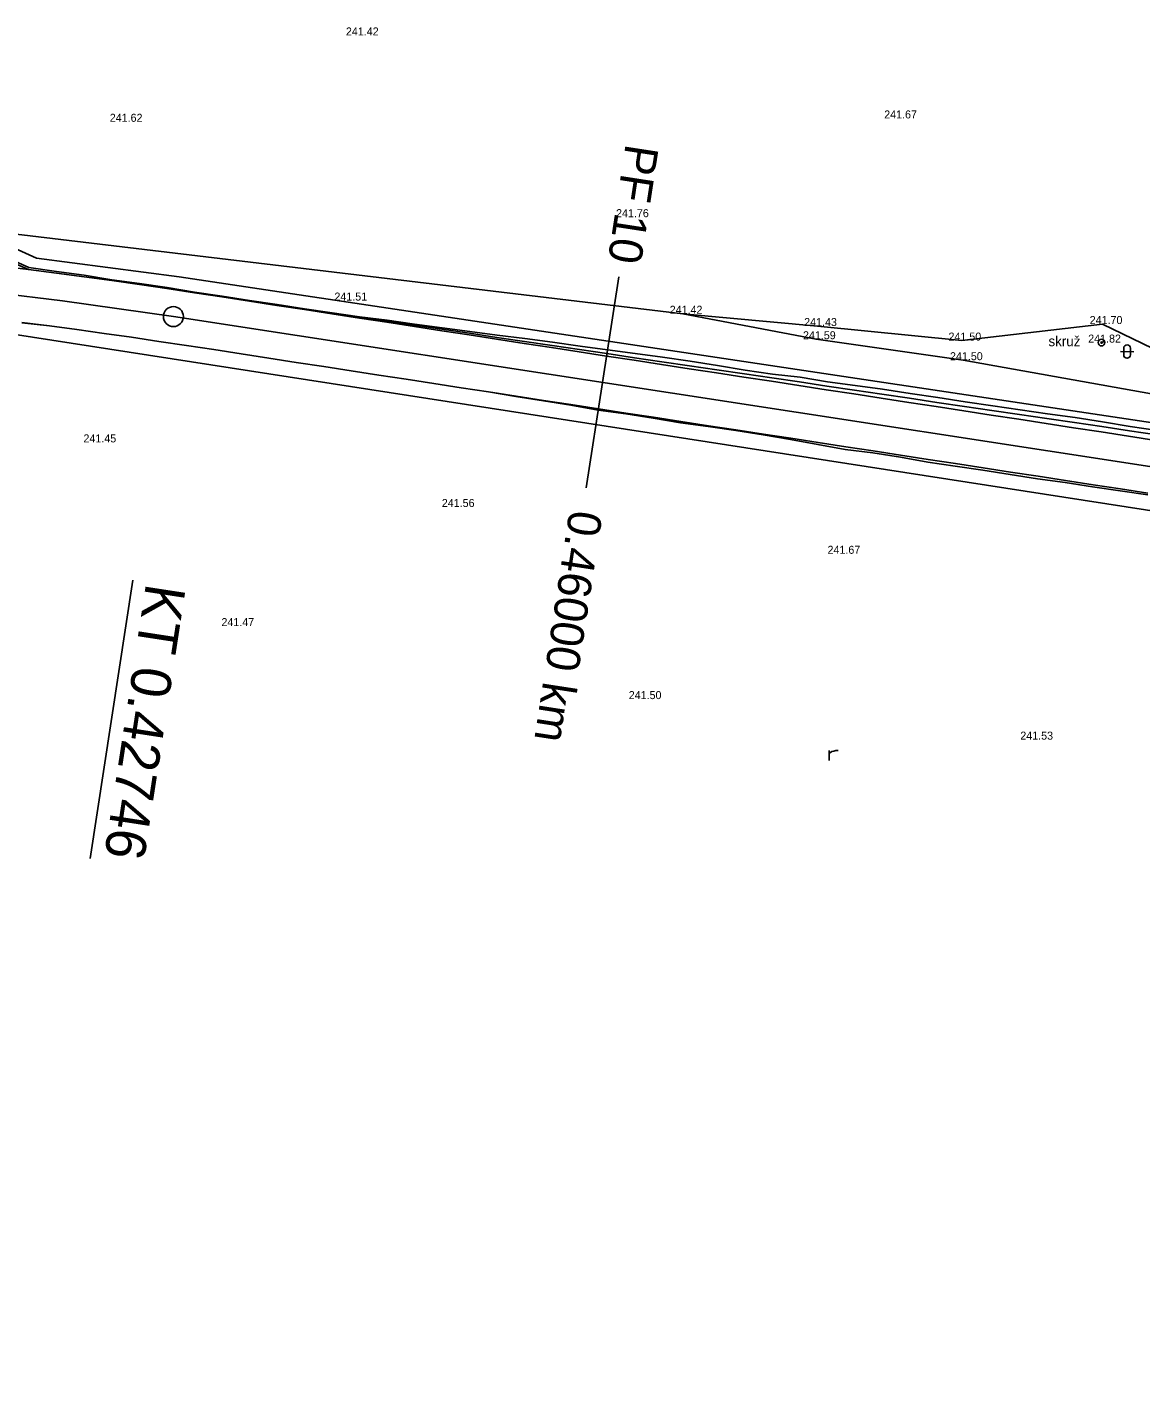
# Model space of a CAD drawing. Extents: x -555887 to -552101, y -1100251 to -1096546.
# Drawn here: x -554264.7 to -554181.3, y -1098461.3 to -1098358.9 of the extents above; entities that cross this region are included whole.
import ezdxf

# ---------------------------------------------------------------- set-up
doc = ezdxf.new("R2010")
doc.units = 0
for name, color, linetype in [('PARCELY_cesty', 7, 'Continuous'), ('POLYGONY_SITUACE_PF', 7, 'Continuous'), ('POLYGONY_SITUACE_PF_POPISY', 7, 'Continuous'), ('POLYGONY_SITUACE_PO', 7, 'Continuous'), ('Výškopis', 7, 'Continuous'), ('ZSST', 7, 'Continuous'), ('zájem', 7, 'Continuous')]:
    doc.layers.add(name, color=color, linetype=linetype)

msp = doc.modelspace()

# ---------------------------------------------------------------- linework, layer by layer
msp.add_line((-554256.8, -1098400.3), (-554260, -1098421.15))
at = {"layer": 'PARCELY_cesty'}
msp.add_lwpolyline([(-554666.58, -1098424.3), (-554661.61, -1098426.35), (-554474.62, -1098365.56), (-554470, -1098364.25), (-554462.92, -1098363), (-554455.97, -1098362.75), (-554451.05, -1098362.62), (-554296.95, -1098373.16), (-554290.89, -1098371.6), (-554270.39, -1098373.3), (-554264.04, -1098376.17), (-554253.34, -1098377.56), (-554081.03, -1098403.4), (-554065.66, -1098405.31), (-554039.82, -1098406.01), (-554011.2, -1098408.42), (-553994.13, -1098410.89)], dxfattribs=at)
at = {"layer": 'POLYGONY_SITUACE_PF'}
for p, q in [((-554220.39, -1098377.57), (-554221.6, -1098385.47)), ((-554221.6, -1098385.47), (-554222.82, -1098393.38))]:
    msp.add_line(p, q, dxfattribs=at)
at = {"layer": 'POLYGONY_SITUACE_PO'}
for p, q in [((-554266.63, -1098376.14), (-554264.62, -1098377.01)), ((-554266.6, -1098375.95), (-554264.6, -1098376.87)), ((-554266.7, -1098376.75), (-554264.62, -1098377.01)), ((-554264.62, -1098377.01), (-554262.54, -1098377.28)), ((-554264.62, -1098377.01), (-554262.54, -1098377.28)), ((-554264.6, -1098376.87), (-554262.53, -1098377.17)), ((-554262.54, -1098377.28), (-554260.47, -1098377.55)), ((-554262.54, -1098377.28), (-554260.47, -1098377.55)), ((-554262.53, -1098377.17), (-554260.45, -1098377.44)), ((-554260.45, -1098377.44), (-554258.39, -1098377.78)), ((-554270.44, -1098378.33), (-554262.09, -1098379.35)), ((-554260.47, -1098377.55), (-554258.39, -1098377.83)), ((-554260.47, -1098377.55), (-554258.39, -1098377.83)), ((-554258.39, -1098377.78), (-554256.31, -1098378.05)), ((-554258.39, -1098377.83), (-554256.32, -1098378.13)), ((-554258.39, -1098377.83), (-554256.32, -1098378.13)), ((-554256.32, -1098378.13), (-554254.25, -1098378.44)), ((-554256.32, -1098378.13), (-554254.25, -1098378.44)), ((-554256.31, -1098378.05), (-554254.24, -1098378.37)), ((-554254.25, -1098378.44), (-554252.19, -1098378.75)), ((-554254.25, -1098378.44), (-554252.19, -1098378.75)), ((-554254.24, -1098378.37), (-554252.18, -1098378.7)), ((-554262.09, -1098379.35), (-554253.77, -1098380.54)), ((-554252.19, -1098378.75), (-554250.13, -1098379.05)), ((-554252.19, -1098378.75), (-554250.13, -1098379.07)), ((-554252.18, -1098378.7), (-554250.12, -1098379.01)), ((-554250.13, -1098379.05), (-554248.06, -1098379.36)), ((-554250.13, -1098379.07), (-554248.07, -1098379.39)), ((-554250.12, -1098379.01), (-554248.06, -1098379.33)), ((-554248.07, -1098379.39), (-554246.01, -1098379.7)), ((-554248.06, -1098379.33), (-554246, -1098379.64)), ((-554248.06, -1098379.36), (-554246, -1098379.66)), ((-554253.77, -1098380.54), (-554081.59, -1098406.98)), ((-554246.01, -1098379.7), (-554243.95, -1098380.02)), ((-554246, -1098379.64), (-554243.94, -1098379.95)), ((-554246, -1098379.66), (-554243.94, -1098379.96)), ((-554243.95, -1098380.02), (-554241.89, -1098380.34)), ((-554243.94, -1098379.95), (-554241.88, -1098380.26)), ((-554243.94, -1098379.96), (-554241.88, -1098380.27)), ((-554241.89, -1098380.34), (-554239.83, -1098380.65)), ((-554241.88, -1098380.26), (-554239.82, -1098380.57)), ((-554241.88, -1098380.27), (-554239.82, -1098380.57)), ((-554265.12, -1098380.98), (-554263.06, -1098381.24)), ((-554265.12, -1098380.98), (-554263.06, -1098381.24)), ((-554265.12, -1098381.02), (-554263.06, -1098381.24)), ((-554263.06, -1098381.24), (-554261.01, -1098381.51)), ((-554263.06, -1098381.24), (-554263.06, -1098381.24)), ((-554263.06, -1098381.24), (-554261.01, -1098381.51)), ((-554263.06, -1098381.24), (-554261.01, -1098381.51)), ((-554261.01, -1098381.51), (-554258.95, -1098381.8)), ((-554261.01, -1098381.51), (-554258.95, -1098381.8)), ((-554261.01, -1098381.51), (-554258.95, -1098381.8)), ((-554239.83, -1098380.65), (-554237.77, -1098380.97)), ((-554239.82, -1098380.57), (-554237.75, -1098380.81)), ((-554239.82, -1098380.57), (-554237.76, -1098380.88)), ((-554237.77, -1098380.97), (-554235.71, -1098381.28)), ((-554237.76, -1098380.88), (-554235.7, -1098381.18)), ((-554237.75, -1098380.81), (-554235.69, -1098381.12)), ((-554235.71, -1098381.28), (-554233.65, -1098381.6)), ((-554235.7, -1098381.18), (-554233.64, -1098381.49)), ((-554235.69, -1098381.12), (-554233.62, -1098381.38)), ((-554233.64, -1098381.49), (-554231.58, -1098381.79)), ((-554233.62, -1098381.38), (-554231.56, -1098381.66)), ((-554258.95, -1098381.8), (-554256.9, -1098382.09)), ((-554258.95, -1098381.8), (-554256.9, -1098382.09)), ((-554258.95, -1098381.8), (-554256.9, -1098382.09)), ((-554256.9, -1098382.09), (-554254.85, -1098382.4)), ((-554256.9, -1098382.09), (-554254.85, -1098382.4)), ((-554256.9, -1098382.09), (-554254.85, -1098382.4)), ((-554254.85, -1098382.4), (-554252.79, -1098382.71)), ((-554254.85, -1098382.4), (-554252.79, -1098382.71)), ((-554254.85, -1098382.4), (-554252.79, -1098382.71)), ((-554233.65, -1098381.6), (-554231.6, -1098381.92)), ((-554231.6, -1098381.92), (-554229.54, -1098382.23)), ((-554231.58, -1098381.79), (-554229.52, -1098382.1)), ((-554231.56, -1098381.66), (-554229.49, -1098381.94)), ((-554229.54, -1098382.23), (-554227.48, -1098382.55)), ((-554229.52, -1098382.1), (-554227.45, -1098382.4)), ((-554229.49, -1098381.94), (-554227.42, -1098382.19)), ((-554227.48, -1098382.55), (-554225.42, -1098382.87)), ((-554227.45, -1098382.4), (-554225.39, -1098382.7)), ((-554227.42, -1098382.19), (-554225.36, -1098382.47)), ((-554225.36, -1098382.47), (-554223.29, -1098382.75)), ((-554252.79, -1098382.71), (-554250.74, -1098383.02)), ((-554252.79, -1098382.71), (-554250.74, -1098383.02)), ((-554252.79, -1098382.71), (-554250.74, -1098383.02)), ((-554250.74, -1098383.02), (-554248.68, -1098383.34)), ((-554250.74, -1098383.02), (-554248.68, -1098383.34)), ((-554250.74, -1098383.02), (-554248.68, -1098383.34)), ((-554248.68, -1098383.34), (-554246.62, -1098383.66)), ((-554248.68, -1098383.34), (-554246.62, -1098383.66)), ((-554248.68, -1098383.34), (-554246.62, -1098383.66)), ((-554225.42, -1098382.87), (-554223.36, -1098383.18)), ((-554225.39, -1098382.7), (-554223.33, -1098383.01)), ((-554223.36, -1098383.18), (-554221.3, -1098383.5)), ((-554223.33, -1098383.01), (-554221.27, -1098383.31)), ((-554223.29, -1098382.75), (-554221.23, -1098383.04)), ((-554221.3, -1098383.5), (-554219.24, -1098383.81)), ((-554221.27, -1098383.31), (-554219.21, -1098383.62)), ((-554221.23, -1098383.04), (-554219.16, -1098383.3)), ((-554219.21, -1098383.62), (-554217.15, -1098383.92)), ((-554219.16, -1098383.3), (-554217.1, -1098383.58)), ((-554217.1, -1098383.58), (-554215.04, -1098383.89)), ((-554246.62, -1098383.66), (-554244.56, -1098383.97)), ((-554246.62, -1098383.66), (-554244.56, -1098383.97)), ((-554246.62, -1098383.66), (-554244.56, -1098383.97)), ((-554244.56, -1098383.97), (-554242.5, -1098384.29)), ((-554244.56, -1098383.97), (-554242.5, -1098384.29)), ((-554244.56, -1098383.97), (-554242.5, -1098384.29)), ((-554242.5, -1098384.29), (-554240.44, -1098384.61)), ((-554242.5, -1098384.29), (-554240.44, -1098384.61)), ((-554242.5, -1098384.29), (-554240.44, -1098384.61)), ((-554240.44, -1098384.61), (-554238.38, -1098384.92)), ((-554240.44, -1098384.61), (-554238.38, -1098384.92)), ((-554240.44, -1098384.61), (-554238.38, -1098384.92)), ((-554219.24, -1098383.81), (-554217.18, -1098384.13)), ((-554217.18, -1098384.13), (-554215.12, -1098384.45)), ((-554217.15, -1098383.92), (-554215.09, -1098384.23)), ((-554215.12, -1098384.45), (-554213.06, -1098384.76)), ((-554215.09, -1098384.23), (-554213.03, -1098384.53)), ((-554215.04, -1098383.89), (-554212.98, -1098384.21)), ((-554213.03, -1098384.53), (-554210.97, -1098384.83)), ((-554212.98, -1098384.21), (-554210.92, -1098384.56)), ((-554210.92, -1098384.56), (-554208.86, -1098384.85)), ((-554238.38, -1098384.92), (-554236.32, -1098385.24)), ((-554238.38, -1098384.92), (-554236.32, -1098385.24)), ((-554238.38, -1098384.92), (-554236.32, -1098385.24)), ((-554236.32, -1098385.24), (-554234.26, -1098385.55)), ((-554236.32, -1098385.24), (-554234.26, -1098385.55)), ((-554236.32, -1098385.24), (-554234.26, -1098385.55)), ((-554234.26, -1098385.55), (-554232.2, -1098385.87)), ((-554234.26, -1098385.55), (-554232.2, -1098385.87)), ((-554234.26, -1098385.55), (-554232.2, -1098385.87)), ((-554213.06, -1098384.76), (-554211, -1098385.08)), ((-554211, -1098385.08), (-554208.94, -1098385.39)), ((-554210.97, -1098384.83), (-554208.91, -1098385.14)), ((-554208.94, -1098385.39), (-554206.89, -1098385.71)), ((-554208.91, -1098385.14), (-554206.84, -1098385.44)), ((-554208.86, -1098384.85), (-554206.79, -1098385.08)), ((-554206.84, -1098385.44), (-554204.78, -1098385.75)), ((-554206.79, -1098385.08), (-554204.74, -1098385.43)), ((-554204.74, -1098385.43), (-554202.67, -1098385.71)), ((-554232.2, -1098385.87), (-554230.14, -1098386.19)), ((-554232.2, -1098385.87), (-554230.14, -1098386.19)), ((-554232.2, -1098385.87), (-554230.14, -1098386.19)), ((-554230.14, -1098386.19), (-554228.08, -1098386.5)), ((-554230.14, -1098386.19), (-554230.14, -1098386.19)), ((-554230.14, -1098386.19), (-554228.09, -1098386.53)), ((-554230.14, -1098386.19), (-554228.08, -1098386.5)), ((-554228.09, -1098386.53), (-554226.03, -1098386.86)), ((-554228.08, -1098386.5), (-554226.03, -1098386.82)), ((-554228.08, -1098386.5), (-554226.03, -1098386.82)), ((-554206.89, -1098385.71), (-554204.83, -1098386.03)), ((-554204.83, -1098386.03), (-554202.77, -1098386.34)), ((-554204.78, -1098385.75), (-554202.72, -1098386.05)), ((-554202.77, -1098386.34), (-554200.71, -1098386.66)), ((-554202.72, -1098386.05), (-554200.66, -1098386.36)), ((-554202.67, -1098385.71), (-554200.61, -1098385.99)), ((-554200.71, -1098386.66), (-554198.65, -1098386.98)), ((-554200.66, -1098386.36), (-554198.6, -1098386.66)), ((-554200.61, -1098385.99), (-554198.55, -1098386.31)), ((-554198.6, -1098386.66), (-554196.54, -1098386.97)), ((-554198.55, -1098386.31), (-554196.48, -1098386.6)), ((-554196.48, -1098386.6), (-554194.42, -1098386.92)), ((-554226.03, -1098386.82), (-554223.97, -1098387.13)), ((-554226.03, -1098386.82), (-554223.97, -1098387.13)), ((-554226.03, -1098386.86), (-554223.97, -1098387.19)), ((-554223.97, -1098387.13), (-554221.91, -1098387.45)), ((-554223.97, -1098387.13), (-554221.91, -1098387.45)), ((-554223.97, -1098387.19), (-554221.92, -1098387.55)), ((-554221.92, -1098387.55), (-554219.86, -1098387.84)), ((-554221.91, -1098387.45), (-554219.85, -1098387.77)), ((-554221.91, -1098387.45), (-554219.85, -1098387.77)), ((-554198.65, -1098386.98), (-554196.59, -1098387.29)), ((-554196.59, -1098387.29), (-554194.53, -1098387.61)), ((-554196.54, -1098386.97), (-554194.48, -1098387.27)), ((-554194.53, -1098387.61), (-554192.47, -1098387.92)), ((-554194.48, -1098387.27), (-554192.42, -1098387.57)), ((-554194.42, -1098386.92), (-554192.36, -1098387.23)), ((-554192.42, -1098387.57), (-554190.36, -1098387.88)), ((-554192.36, -1098387.23), (-554190.3, -1098387.52)), ((-554190.3, -1098387.52), (-554188.24, -1098387.82)), ((-554219.86, -1098387.84), (-554217.8, -1098388.16)), ((-554219.85, -1098387.77), (-554217.79, -1098388.08)), ((-554219.85, -1098387.77), (-554217.79, -1098388.08)), ((-554217.8, -1098388.16), (-554215.75, -1098388.51)), ((-554217.79, -1098388.08), (-554215.73, -1098388.4)), ((-554217.79, -1098388.08), (-554215.73, -1098388.4)), ((-554215.75, -1098388.51), (-554213.68, -1098388.79)), ((-554215.73, -1098388.4), (-554213.67, -1098388.72)), ((-554215.73, -1098388.4), (-554213.67, -1098388.72)), ((-554213.67, -1098388.72), (-554211.61, -1098389.03)), ((-554213.67, -1098388.72), (-554211.61, -1098389.03)), ((-554192.47, -1098387.92), (-554190.41, -1098388.24)), ((-554190.41, -1098388.24), (-554188.35, -1098388.56)), ((-554190.36, -1098387.88), (-554188.3, -1098388.18)), ((-554188.35, -1098388.56), (-554186.29, -1098388.87)), ((-554188.3, -1098388.18), (-554186.23, -1098388.49)), ((-554188.24, -1098387.82), (-554186.18, -1098388.11)), ((-554186.23, -1098388.49), (-554184.17, -1098388.79)), ((-554186.18, -1098388.11), (-554184.12, -1098388.44)), ((-554184.12, -1098388.44), (-554182.06, -1098388.77)), ((-554213.68, -1098388.79), (-554211.62, -1098389.09)), ((-554211.62, -1098389.09), (-554209.56, -1098389.41)), ((-554211.61, -1098389.03), (-554209.55, -1098389.35)), ((-554211.61, -1098389.03), (-554209.55, -1098389.35)), ((-554209.56, -1098389.41), (-554207.51, -1098389.76)), ((-554209.55, -1098389.35), (-554207.49, -1098389.66)), ((-554209.55, -1098389.35), (-554207.49, -1098389.66)), ((-554207.51, -1098389.76), (-554205.46, -1098390.13)), ((-554207.49, -1098389.66), (-554205.43, -1098389.98)), ((-554207.49, -1098389.66), (-554205.43, -1098389.98)), ((-554186.29, -1098388.87), (-554184.23, -1098389.19)), ((-554184.23, -1098389.19), (-554182.18, -1098389.51)), ((-554184.17, -1098388.79), (-554182.11, -1098389.1)), ((-554182.18, -1098389.51), (-554180.12, -1098389.82)), ((-554182.11, -1098389.1), (-554180.05, -1098389.4)), ((-554182.06, -1098388.77), (-554180, -1098389.09)), ((-554205.46, -1098390.13), (-554203.41, -1098390.5)), ((-554205.43, -1098389.98), (-554203.37, -1098390.3)), ((-554205.43, -1098389.98), (-554203.37, -1098390.3)), ((-554203.41, -1098390.5), (-554201.34, -1098390.76)), ((-554203.37, -1098390.3), (-554201.31, -1098390.61)), ((-554203.37, -1098390.3), (-554201.31, -1098390.61)), ((-554201.34, -1098390.76), (-554199.28, -1098391.07)), ((-554201.31, -1098390.61), (-554199.26, -1098390.93)), ((-554201.31, -1098390.61), (-554199.26, -1098390.93)), ((-554199.28, -1098391.07), (-554197.23, -1098391.44)), ((-554199.26, -1098390.93), (-554197.2, -1098391.25)), ((-554199.26, -1098390.93), (-554197.2, -1098391.25)), ((-554197.23, -1098391.44), (-554195.17, -1098391.75)), ((-554197.2, -1098391.25), (-554195.14, -1098391.56)), ((-554197.2, -1098391.25), (-554195.14, -1098391.56)), ((-554195.17, -1098391.75), (-554193.11, -1098392.06)), ((-554195.14, -1098391.56), (-554193.08, -1098391.88)), ((-554195.14, -1098391.56), (-554193.08, -1098391.88)), ((-554193.11, -1098392.06), (-554191.05, -1098392.37)), ((-554193.08, -1098391.88), (-554191.02, -1098392.19)), ((-554193.08, -1098391.88), (-554191.02, -1098392.19)), ((-554191.05, -1098392.37), (-554188.99, -1098392.69)), ((-554191.02, -1098392.19), (-554188.96, -1098392.51)), ((-554191.02, -1098392.19), (-554188.96, -1098392.51)), ((-554188.99, -1098392.69), (-554186.92, -1098392.98)), ((-554188.96, -1098392.51), (-554186.9, -1098392.83)), ((-554188.96, -1098392.51), (-554186.9, -1098392.83)), ((-554186.9, -1098392.83), (-554184.84, -1098393.14)), ((-554186.9, -1098392.83), (-554184.84, -1098393.14)), ((-554186.92, -1098392.98), (-554184.87, -1098393.31)), ((-554184.87, -1098393.31), (-554182.81, -1098393.61)), ((-554184.84, -1098393.14), (-554182.78, -1098393.46)), ((-554184.84, -1098393.14), (-554182.78, -1098393.46)), ((-554182.81, -1098393.61), (-554180.74, -1098393.9)), ((-554182.78, -1098393.46), (-554180.72, -1098393.78)), ((-554182.78, -1098393.46), (-554180.72, -1098393.78))]:
    msp.add_line(p, q, dxfattribs=at)
msp.add_circle((-554253.77, -1098380.54), 0.75, dxfattribs=at)
at = {"layer": 'ZSST'}
for p, q in [((-554182.79, -1098383.16), (-554181.79, -1098383.17)), ((-554182.54, -1098382.91), (-554182.54, -1098383.41)), ((-554182.04, -1098382.91), (-554182.04, -1098383.41))]:
    msp.add_line(p, q, dxfattribs=at)
for points in [[(-554664.51, -1098427.29), (-554593.24, -1098405.5), (-554564.12, -1098396.39), (-554504.51, -1098380.38), (-554474.09, -1098371.8), (-554453.04, -1098367.02), (-554440.1, -1098364.81), (-554432.74, -1098364.37), (-554410.92, -1098364.7), (-554369.44, -1098366), (-554333.38, -1098368), (-554270.17, -1098373.82), (-554215.58, -1098380.33), (-554205.6, -1098382.24), (-554194.57, -1098383.81), (-554169.13, -1098388.36), (-554184.13, -1098381.1), (-554194.68, -1098382.34), (-554205.5, -1098381.25), (-554215.58, -1098380.33)], [(-554204.62, -1098413.8), (-554204.62, -1098413.07)], [(-554204.62, -1098413.3), (-554204.52, -1098413.21), (-554204.42, -1098413.14), (-554204.26, -1098413.1), (-554204.11, -1098413.07), (-554203.95, -1098413.07)]]:
    msp.add_lwpolyline(points, dxfattribs=at)
for radius in [0.25, 0.05]:
    msp.add_circle((-554184.2, -1098382.49), radius, dxfattribs=at)
for centre, start, end in [((-554182.29, -1098382.91), 359.7942, 179.7942), ((-554182.29, -1098383.41), 179.7942, 359.7942)]:
    msp.add_arc(centre, 0.25, start, end, dxfattribs=at)
at = {"layer": 'zájem'}
for points in [[(-554271.92, -1098380.9), (-554131.79, -1098402.65), (-553999.67, -1098421.44), (-553991.3, -1098421.75), (-553988.01, -1098422.96), (-553982.15, -1098425.12), (-553979.24, -1098426.19), (-554050.69, -1098691.93)], [(-554050.69, -1098691.93), (-553979.24, -1098426.19), (-553982.15, -1098425.12), (-553988.01, -1098422.96), (-553991.3, -1098421.75), (-553999.67, -1098421.44), (-554131.79, -1098402.65), (-554271.92, -1098380.9)]]:
    msp.add_lwpolyline(points, dxfattribs=at)

# ---------------------------------------------------------------- texts
msp.add_text('KT 0.42746', height=3, rotation=261.2697).set_placement((-554255.81, -1098400.46))
at = {"layer": 'POLYGONY_SITUACE_PF_POPISY'}
for s, p in [('PF 10', (-554219.86, -1098367.53)), ('0.46000 km', (-554224.07, -1098394.96))]:
    msp.add_text(s, height=2.5, rotation=261.2697, dxfattribs=at).set_placement(p)
at = {"layer": 'Výškopis'}
for s, p in [('241.42', (-554240.84, -1098359.47)), ('241.67', (-554200.49, -1098365.69)), ('241.62', (-554258.54, -1098365.94)), ('241.76', (-554220.59, -1098373.09)), ('241.51', (-554241.7, -1098379.34)), ('241.42', (-554216.57, -1098380.33)), ('241.70', (-554185.09, -1098381.1)), ('241.43', (-554206.49, -1098381.25)), ('241.59', (-554206.58, -1098382.24)), ('241.50', (-554195.67, -1098382.34)), ('241.82', (-554185.2, -1098382.49)), ('241.50', (-554195.56, -1098383.81)), ('241.45', (-554260.51, -1098389.97)), ('241.56', (-554233.65, -1098394.81)), ('241.67', (-554204.74, -1098398.32)), ('241.47', (-554250.17, -1098403.74)), ('241.50', (-554219.64, -1098409.21)), ('241.53', (-554190.29, -1098412.25))]:
    msp.add_text(s, height=0.6, dxfattribs=at).set_placement(p)
at = {"layer": 'ZSST'}
msp.add_text('skruž', height=0.75, dxfattribs=at).set_placement((-554188.18, -1098382.76))

doc.saveas('drawing.dxf')
